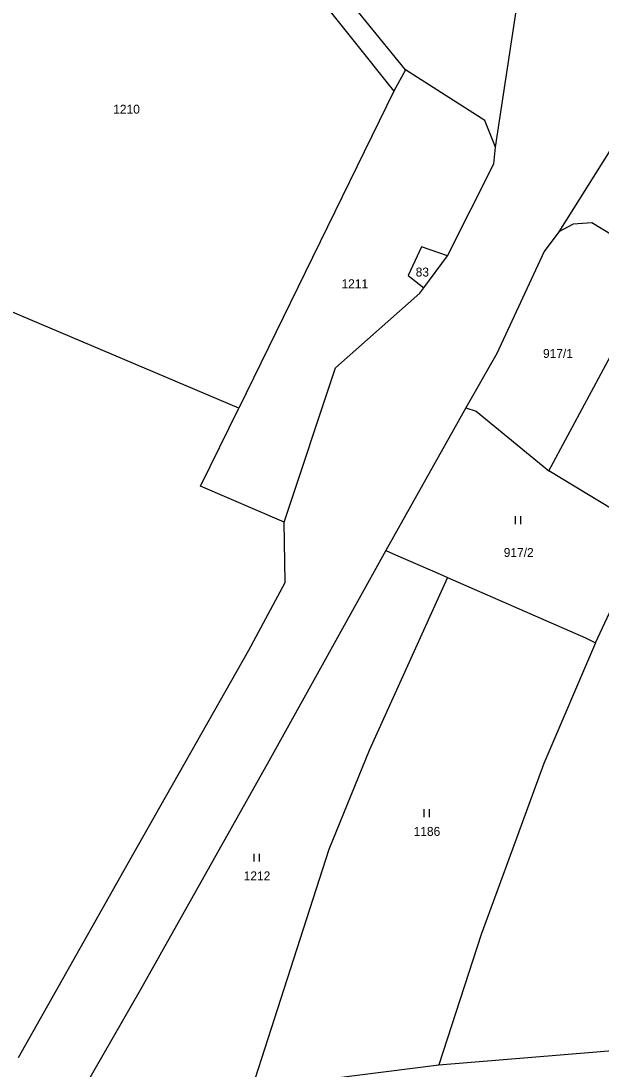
# Model space of a CAD drawing. Extents: x -746176 to -739709, y -1127410 to -1124482.
# Drawn here: x -742787.6 to -742677.4, y -1125952.1 to -1125753.1 of the extents above; entities that cross this region are included whole.
import ezdxf

# ---------------------------------------------------------------- set-up
doc = ezdxf.new("R2010")
doc.units = 0
for name, color, linetype in [('Hranice parcel', 7, 'Continuous'), ('Parcelní čísla', 7, 'Continuous'), ('Značky kultur', 7, 'Continuous')]:
    doc.layers.add(name, color=color, linetype=linetype)

msp = doc.modelspace()

# ---------------------------------------------------------------- linework, layer by layer
at = {"layer": 'Hranice parcel'}
for p, q in [((-742697.47, -1125777.04), (-742693.19, -1125749.09)), ((-742746.23, -1125826.62), (-742913.85, -1125755.51)), ((-742714.55, -1125762.38), (-742716.78, -1125766.45)), ((-742666.57, -1125763.1), (-742685.44, -1125793.17)), ((-742716.78, -1125766.45), (-742746.23, -1125826.62)), ((-742711.08, -1125803.8), (-742706.54, -1125797.7)), ((-742687.34, -1125838.54), (-742666.73, -1125800.21)), ((-742703.06, -1125826.53), (-742718.28, -1125853.63)), ((-742668.52, -1125849.93), (-742687.34, -1125838.54)), ((-742678.43, -1125871.17), (-742673.57, -1125860.74)), ((-742708.2, -1125951.28), (-742672.18, -1125948.29)), ((-742743.77, -1125955.79), (-742708.2, -1125951.28))]:
    msp.add_line(p, q, dxfattribs=at)
for points in [[(-742714.55, -1125762.38), (-742729.59, -1125743.86), (-742745.51, -1125727.03), (-742789.4, -1125685.29), (-742799.96, -1125676.5), (-742797.78, -1125673.65), (-742804.75, -1125668.98), (-742814.6, -1125664.12), (-742816.05, -1125666.93)], [(-742787.81, -1125703.29), (-742771.53, -1125708.51), (-742748.64, -1125729.55), (-742732.87, -1125746.24), (-742716.78, -1125766.45)], [(-742697.47, -1125777.04), (-742699.45, -1125771.99), (-742714.55, -1125762.38)], [(-742706.54, -1125797.7), (-742697.79, -1125780.22), (-742697.47, -1125777.04)], [(-742685.44, -1125793.17), (-742688.23, -1125796.88), (-742697.22, -1125816.25), (-742703.06, -1125826.53)], [(-742666.73, -1125800.21), (-742675.28, -1125793.75), (-742679.14, -1125791.44), (-742682.72, -1125791.66), (-742685.44, -1125793.17)], [(-742706.54, -1125797.7), (-742711.51, -1125795.96), (-742714.07, -1125801.41), (-742711.08, -1125803.8)], [(-742737.61, -1125848.28), (-742727.85, -1125818.95), (-742711.83, -1125804.77), (-742711.08, -1125803.8)], [(-742737.61, -1125848.28), (-742753.49, -1125841.45), (-742746.23, -1125826.62)], [(-742703.06, -1125826.53), (-742701.11, -1125827.19), (-742687.34, -1125838.54)], [(-742788.09, -1125949.88), (-742766.63, -1125911.85), (-742744.3, -1125872.58), (-742737.39, -1125859.72), (-742737.61, -1125848.28)], [(-742718.28, -1125853.63), (-742740.52, -1125893.64), (-742764.97, -1125937.08), (-742775.44, -1125955.39)], [(-742718.28, -1125853.63), (-742716.45, -1125854.43), (-742707.99, -1125858.13), (-742706.55, -1125858.76)], [(-742706.55, -1125858.76), (-742721.46, -1125891.59), (-742729.1, -1125910.37), (-742743.77, -1125955.79)], [(-742706.55, -1125858.76), (-742680.36, -1125870.24), (-742678.43, -1125871.17)], [(-742678.43, -1125871.17), (-742688.24, -1125894.1), (-742694.2, -1125910.33), (-742700.15, -1125926.56), (-742708.2, -1125951.28)]]:
    msp.add_lwpolyline(points, dxfattribs=at)
at = {"layer": 'Značky kultur'}
for p, q in [((-742693.621, -1125848.61), (-742693.621, -1125847.11)), ((-742692.62, -1125848.61), (-742692.62, -1125847.11)), ((-742711.011, -1125904.26), (-742711.011, -1125902.76)), ((-742710.01, -1125904.26), (-742710.01, -1125902.76)), ((-742743.291, -1125912.7), (-742743.291, -1125911.2)), ((-742742.29, -1125912.7), (-742742.29, -1125911.2))]:
    msp.add_line(p, q, dxfattribs=at)

# ---------------------------------------------------------------- texts
at = {"layer": 'Parcelní čísla'}
for s, p in [('1210', (-742770.077, -1125770.71)), ('83', (-742712.612, -1125801.63)), ('1211', (-742726.707, -1125803.85)), ('917/1', (-742688.423, -1125817.08)), ('917/2', (-742695.883, -1125854.86)), ('1186', (-742713.007, -1125907.81)), ('1212', (-742745.287, -1125916.25))]:
    msp.add_text(s, height=1.7, dxfattribs=at).set_placement(p)

doc.saveas('drawing.dxf')
